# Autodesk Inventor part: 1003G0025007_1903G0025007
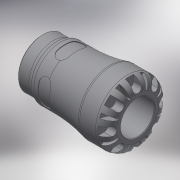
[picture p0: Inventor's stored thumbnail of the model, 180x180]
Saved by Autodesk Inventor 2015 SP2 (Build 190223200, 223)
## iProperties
Created: 2016-12
Part Number: 1003G0025007_1903G0025007
Material: Generic
Description: PLASSON FEMALE ADAPTOR 25X3/4" SERIES 1
Document SubType Name: Modeling
Designer: KIM
Mass: 664.223 g
Surface Area: 733.008 cm^2
Volume: 474.445 cm^3
Density: 1 g/cm^3
Appearance: Default
Author: KIM
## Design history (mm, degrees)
derived "1003G.ipt"
feature "Solid1::1003G.ipt"
tag "TaggingFeature1"
body "Solid1"
other parameters: "d0" = 71, "d1" = 20.16, "d2" = 25, "d3" = 31.25, "d4" = 47, "d6" = 48, "d8" = 39.95, "d13" = 6.3, "d14" = 6.3, "d15" = 0, "d17" = 360 deg, "d19" = 8 deg, "d20" = 0.5, "d21" = 0.5, "d22" = 8 deg, "d24" = 0, "d26" = 360 deg, "d32" = 4.7, "d33" = 4.7, "d39" = 0.72351, "d42" = 24.117, "d43" = 36.66, "d46" = 2.08333, "d47" = 12, "d48" = 22.91115, "d50" = 3.63, "d51" = 0.47, "d54" = 8.75, "d55" = 5.5, "d57" = 12.348, "d58" = 0, "d68" = 360 deg, "d72" = 0.5, "d74" = 0, "d76" = 7.4375, "d_" = 25, "E_" = 47, "H_" = 71, "l_" = 48, "G_" = 24.117, "l_2" = 12, "d9" = 7.875, "d11" = 47, "d12" = 31.25, "d49" = 11
